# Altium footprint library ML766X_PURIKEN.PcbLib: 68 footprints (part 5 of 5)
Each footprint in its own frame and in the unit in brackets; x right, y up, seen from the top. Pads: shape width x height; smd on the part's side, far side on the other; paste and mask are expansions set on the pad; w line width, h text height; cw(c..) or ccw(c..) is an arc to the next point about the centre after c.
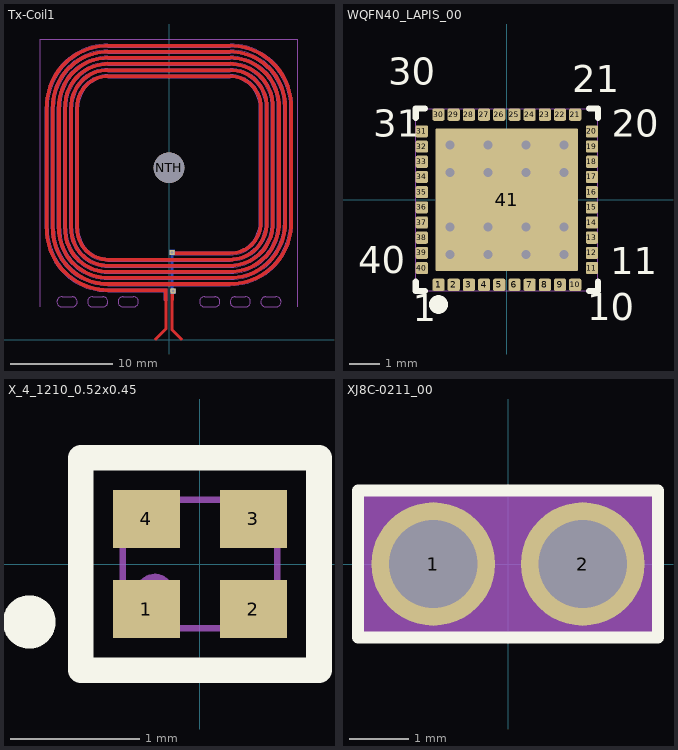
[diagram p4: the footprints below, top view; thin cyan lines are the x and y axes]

## Tx-Coil1 [mm]
pads (5):
  rrect20% 0.5x0.5 smd far side: 0.5*0.5(0.3,8.55) 0.5*0.5(0.4,4.75)
  rect 0.5x0.5 hole 0.3: 1(0.4,4.75) 2(0.3,8.55)
  round 3 hole 3 unplated mask+0.25: NTH(0,16.85)
Top Layer:
  region: 0.45,3.85 0.45,5 0.15,5 0.15,3.85
  region: 742 vertices and 0 holes, not listed, extent -12.15,3.85 12.15,29
  lines w0.3: -1.3,0.05 -0.3,1.05 -0.3,4.85 ; 0.3,4.75 0.3,0.95 1.2,0.05
Bottom Layer:
  lines w0.3: 0.3,8.55 0.3,6.7 0.3,4.75 0.4,4.75
Mechanical 1:
  lines w0.1: -12.65,3.2 -12.65,29.5 12.65,29.5 12.65,3.2 ; -10.5,3.2 cw(c-10.5,3.7) -10.5,4.2 -9.5,4.2 cw(c-9.5,3.7) -9.5,3.2 -10,3.2 -10.5,3.2 ; -7.5,3.2 cw(c-7.5,3.7) -7.5,4.2 -6.5,4.2 cw(c-6.5,3.7) -6.5,3.2 -7,3.2 -7.5,3.2 ; -4.5,3.2 cw(c-4.5,3.7) -4.5,4.2 -3.5,4.2 cw(c-3.5,3.7) -3.5,3.2 -4,3.2 -4.5,3.2 ; 3.5,3.2 cw(c3.5,3.7) 3.5,4.2 4.5,4.2 cw(c4.5,3.7) 4.5,3.2 4,3.2 3.5,3.2 ; 6.5,3.2 cw(c6.5,3.7) 6.5,4.2 7.5,4.2 cw(c7.5,3.7) 7.5,3.2 7,3.2 6.5,3.2 ; 9.5,3.2 cw(c9.5,3.7) 9.5,4.2 10.5,4.2 cw(c10.5,3.7) 10.5,3.2 10,3.2 9.5,3.2
Top Component Outline:
  lines w0.05: -12.15,10.85 ccw(c-6,10.85) -6,4.7 -0.45,4.7 -0.45,3.85 -0.15,3.85 -0.15,5 -6,5 cw(c-6,10.85) -11.85,10.85 -11.85,22.85 cw(c-6,22.85) -6,28.7 6,28.7 cw(c6,22.85) 11.85,22.85 11.85,11.45 cw(c6,11.45) 6,5.6 -6,5.6 cw(c-6,10.85) -11.25,10.85 -11.25,22.85 cw(c-6,22.85) -6,28.1 6,28.1 cw(c6,22.85) 11.25,22.85 11.25,11.45 cw(c6,11.45) 6,6.2 -6,6.2 cw(c-6,10.85) -10.65,10.85 -10.65,22.85 cw(c-6,22.85) -6,27.5 6,27.5 cw(c6,22.85) 10.65,22.85 10.65,11.45 cw(c6,11.45) 6,6.8 -6,6.8 cw(c-6,10.85) -10.05,10.85 -10.05,22.85 cw(c-6,22.85) -6,26.9 6,26.9 cw(c6,22.85) 10.05,22.85 10.05,11.45 cw(c6,11.45) 6,7.4 -6,7.4 cw(c-6,10.85) -9.45,10.85 -9.45,22.85 cw(c-6,22.85) -6,26.3 6,26.3 cw(c6,22.85) 9.45,22.85 9.45,11.45 cw(c6,11.45) 6,8 -6,8 cw(c-6,10.85) -8.85,10.85 -8.85,22.85 cw(c-6,22.85) -6,25.7 6,25.7 cw(c6,22.85) 8.85,22.85 8.85,11.45 cw(c6,11.45) 6,8.6 0.15,8.6 0.15,8.3 6,8.3 ccw(c6,11.45) 9.15,11.45 9.15,22.85 ccw(c6,22.85) 6,26 -6,26 ccw(c-6,22.85) -9.15,22.85 -9.15,10.85 ccw(c-6,10.85) -6,7.7 6,7.7 ccw(c6,11.45) 9.75,11.45 9.75,22.85 ccw(c6,22.85) 6,26.6 -6,26.6 ccw(c-6,22.85) -9.75,22.85 -9.75,10.85 ccw(c-6,10.85) -6,7.1 6,7.1 ccw(c6,11.45) 10.35,11.45 10.35,22.85 ccw(c6,22.85) 6,27.2 -6,27.2 ccw(c-6,22.85) -10.35,22.85 -10.35,10.85 ccw(c-6,10.85) -6,6.5 6,6.5 ccw(c6,11.45) 10.95,11.45 10.95,22.85 ccw(c6,22.85) 6,27.8 -6,27.8 ccw(c-6,22.85) -10.95,22.85 -10.95,10.85 ccw(c-6,10.85) -6,5.9 6,5.9 ccw(c6,11.45) 11.55,11.45 11.55,22.85 ccw(c6,22.85) 6,28.4 -6,28.4 ccw(c-6,22.85) -11.55,22.85 -11.55,10.85 ccw(c-6,10.85) -6,5.3 6,5.3 ccw(c6,11.45) 12.15,11.45 12.15,22.85 ccw(c6,22.85) 6,29 -6,29 ccw(c-6,22.85) -12.15,22.85 -12.15,10.85

## WQFN40_LAPIS_00 [mm]
height 0.8
pads (57):
  rrect25% 0.4x0.4 smd paste-2539.97 mask+0.025: 1(-2.25,-2.8) 2(-1.75,-2.8) 3(-1.25,-2.8) 4(-0.75,-2.8) 5(-0.25,-2.8) 6(0.25,-2.8) 7(0.75,-2.8) 8(1.25,-2.8) 9(1.75,-2.8) 10(2.25,-2.8) 11(2.8,-2.25) 12(2.8,-1.75) 13(2.8,-1.25) 14(2.8,-0.75) 15(2.8,-0.25) 16(2.8,0.25) 17(2.8,0.75) 18(2.8,1.25) 19(2.8,1.75) 20(2.8,2.25) 21(2.25,2.8) 22(1.75,2.8) 23(1.25,2.8) 24(0.75,2.8) 25(0.25,2.8) 26(-0.25,2.8) 27(-0.75,2.8) 28(-1.25,2.8) 29(-1.75,2.8) 30(-2.25,2.8) 31(-2.8,2.25) 32(-2.8,1.75) 33(-2.8,1.25) 34(-2.8,0.75) 35(-2.8,0.25) 36(-2.8,-0.25) 37(-2.8,-0.75) 38(-2.8,-1.25) 39(-2.8,-1.75) 40(-2.8,-2.25)
  rrect2% 4.7x4.7 smd: 41(0,0)
  round 0.6 / inner round 1.524 / far side round 0.6 hole 0.3 mask-0.051: VIA0.3_0.6_0.6_00(-1.875,-1.8) VIA0.3_0.6_0.6_00(-1.875,-0.9) VIA0.3_0.6_0.6_00(-1.875,0.9) VIA0.3_0.6_0.6_00(-1.875,1.8) VIA0.3_0.6_0.6_00(-0.625,-1.8) VIA0.3_0.6_0.6_00(-0.625,-0.9) VIA0.3_0.6_0.6_00(-0.625,0.9) VIA0.3_0.6_0.6_00(-0.625,1.8) VIA0.3_0.6_0.6_00(0.625,-1.8) VIA0.3_0.6_0.6_00(0.625,-0.9) VIA0.3_0.6_0.6_00(0.625,0.9) VIA0.3_0.6_0.6_00(0.625,1.8) VIA0.3_0.6_0.6_00(1.875,-1.8) VIA0.3_0.6_0.6_00(1.875,-0.9) VIA0.3_0.6_0.6_00(1.875,0.9) VIA0.3_0.6_0.6_00(1.875,1.8)
Top Overlay:
  region: -1.95,-3.45 -1.95,-3.39 -1.996,-3.28 -2.08,-3.196 -2.19,-3.15 -2.31,-3.15 -2.42,-3.196 -2.504,-3.28 -2.55,-3.39 -2.55,-3.51 -2.504,-3.62 -2.42,-3.704 -2.31,-3.75 -2.25,-3.75 -2.19,-3.75 -2.08,-3.704 -1.996,-3.62 -1.95,-3.51 -1.95,-3.39 -1.996,-3.28 -2.08,-3.196 -2.19,-3.15 -2.31,-3.15 -2.42,-3.196 -2.504,-3.28 -2.55,-3.39 -2.55,-3.45 -2.55,-3.51 -2.504,-3.62 -2.42,-3.704 -2.31,-3.75 -2.19,-3.75 -2.08,-3.704 -1.996,-3.62 -1.95,-3.51 -1.95,-3.39 -1.996,-3.28 -2.08,-3.196 -2.19,-3.15 -2.25,-3.15 -2.31,-3.15 -2.42,-3.196 -2.504,-3.28 -2.55,-3.39 -2.55,-3.51 -2.504,-3.62 -2.42,-3.704 -2.31,-3.75 -2.19,-3.75 -2.08,-3.704 -1.996,-3.62 -1.95,-3.51
  lines w0.2: -3,-2.7 -3,-3 -2.7,-3 ; -3,2.7 -3,3 -2.7,3 ; 2.7,-3 3,-3 3,-2.7 ; 2.7,3 3,3 3,2.7
  text "40" at -4.9,-2.717 h1.52
  text "31" at -4.4,1.783 h1.52
  text "30" at -3.9,3.483 h1.52
  text "21" at 2.151,3.25 h1.52
  text "20" at 3.451,1.783 h1.52
  text "11" at 3.4,-2.75 h1.52
  text "10" at 2.65,-4.267 h1.52
  text "1" at -3.1,-4.3 h1.52
MASK:
  region: 2.35,0.15 0.15,0.15 0.15,2.35 2.35,2.35
  region: -2.35,2.35 -0.15,2.35 -0.15,0.15 -2.35,0.15
  region: 2.35,-2.35 0.15,-2.35 0.15,-0.15 2.35,-0.15
  region: -2.35,-0.15 -0.15,-0.15 -0.15,-2.35 -2.35,-2.35
Top Solder:
  region: -3.05,2.5 -2.55,2.5 -2.55,-2.5 -3.05,-2.5
  region: -2.5,3.05 2.5,3.05 2.5,2.55 -2.5,2.55
  region: 2.55,2.5 3.05,2.5 3.05,-2.5 2.55,-2.5
  region: -2.5,-2.55 2.5,-2.55 2.5,-3.05 -2.5,-3.05
  region: -2.4,-2.4 -2.4,2.4 2.4,2.4 2.4,-2.4
Top Component Outline:
  lines w0.01: -3,-3 3,-3 3,3 -3,3 -3,-3
3D body: height 0.8, standoff 0, extent -3,-3 3,3

## X_4_1210_0.52x0.45 [mm] "KYOCERA"
height 0.3
pads (4):
  rect 0.52x0.45 smd: 1(-0.415,-0.35) 2(0.415,-0.35) 3(0.415,0.35) 4(-0.415,0.35)
Top Overlay:
  circle w0.254: c-1.325,-0.45 r0.079
  lines w0.2: -0.925,-0.825 0.925,-0.825 0.925,0.825 -0.925,0.825 -0.925,-0.825
Top Component Outline:
  circle w0.05: c-0.35,-0.225 r0.125
  lines w0.05: -0.6,-0.5 0.6,-0.5 0.6,0.5 -0.6,0.5 -0.6,-0.5
3D body "CX1210SB.step": height 0.3, standoff -0.01, extent -0.6,-0.5 0.6,0.5

## XJ8C-0211_00 [mm]
pads (2):
  round 2.1 / inner round 1.524 / far side round 2.1 hole 1.5: 1(-1.27,0) 2(1.27,0)
Top Overlay:
  lines w0.2: -2.55,-1.25 -2.55,1.25 2.55,1.25 2.55,-1.25 -2.55,-1.25
Top Component Outline:
  dashed: -2.55,1.25 2.55,1.25 2.55,-1.25 -2.55,-1.25
  lines w0.01: -2.55,-1.25 -2.55,1.25 2.55,1.25 2.55,-1.25 -2.55,-1.25
Bottom Component Outline:
  dashed: 2.02,0 2.02,0.111 1.955,0.324 1.832,0.509 1.66,0.65 1.454,0.735 1.233,0.757 1.015,0.714 0.818,0.609 0.661,0.452 0.556,0.255 0.513,0.037 0.535,-0.184 0.62,-0.39 0.761,-0.562 0.946,-0.685 1.159,-0.75 1.27,-0.75 1.381,-0.75 1.594,-0.685 1.779,-0.562 1.92,-0.39 2.005,-0.184 2.027,0.037 1.984,0.255 1.879,0.452 1.722,0.609 1.525,0.714 1.307,0.757 1.086,0.735 0.88,0.65 0.708,0.509 0.585,0.324 0.52,0.111 0.52,0 0.52,-0.111 0.585,-0.324 0.708,-0.509 0.88,-0.65 1.086,-0.735 1.307,-0.757 1.525,-0.714 1.722,-0.609 1.879,-0.452 1.984,-0.255 2.027,-0.037 2.005,0.184 1.92,0.39 1.779,0.562 1.594,0.685 1.381,0.75 1.27,0.75 1.159,0.75 0.946,0.685 0.761,0.562 0.62,0.39 0.535,0.184 0.513,-0.037 0.556,-0.255 0.661,-0.452 0.818,-0.609 1.015,-0.714 1.233,-0.757 1.454,-0.735 1.66,-0.65 1.832,-0.509 1.955,-0.324 2.02,-0.111
  dashed: -0.52,0 -0.52,0.111 -0.585,0.324 -0.708,0.509 -0.88,0.65 -1.086,0.735 -1.307,0.757 -1.525,0.714 -1.722,0.609 -1.879,0.452 -1.984,0.255 -2.027,0.037 -2.005,-0.184 -1.92,-0.39 -1.779,-0.562 -1.594,-0.685 -1.381,-0.75 -1.27,-0.75 -1.159,-0.75 -0.946,-0.685 -0.761,-0.562 -0.62,-0.39 -0.535,-0.184 -0.513,0.037 -0.556,0.255 -0.661,0.452 -0.818,0.609 -1.015,0.714 -1.233,0.757 -1.454,0.735 -1.66,0.65 -1.832,0.509 -1.955,0.324 -2.02,0.111 -2.02,0 -2.02,-0.111 -1.955,-0.324 -1.832,-0.509 -1.66,-0.65 -1.454,-0.735 -1.233,-0.757 -1.015,-0.714 -0.818,-0.609 -0.661,-0.452 -0.556,-0.255 -0.513,-0.037 -0.535,0.184 -0.62,0.39 -0.761,0.562 -0.946,0.685 -1.159,0.75 -1.27,0.75 -1.381,0.75 -1.594,0.685 -1.779,0.562 -1.92,0.39 -2.005,0.184 -2.027,-0.037 -1.984,-0.255 -1.879,-0.452 -1.722,-0.609 -1.525,-0.714 -1.307,-0.757 -1.086,-0.735 -0.88,-0.65 -0.708,-0.509 -0.585,-0.324 -0.52,-0.111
